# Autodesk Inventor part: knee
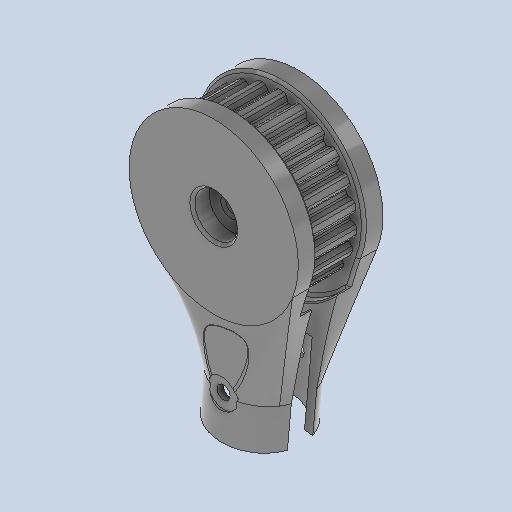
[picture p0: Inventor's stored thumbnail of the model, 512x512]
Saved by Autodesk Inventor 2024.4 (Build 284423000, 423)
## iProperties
Created: 2026-01
Part Number: knee
Material: Generic
Document SubType Name: Modeling
Designer: AdminForWorker
Density: 1 g/cm^3
Appearance: Default
Title: knee
Author: AdminForWorker
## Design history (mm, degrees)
feature "Body1"
body "Solid1"
